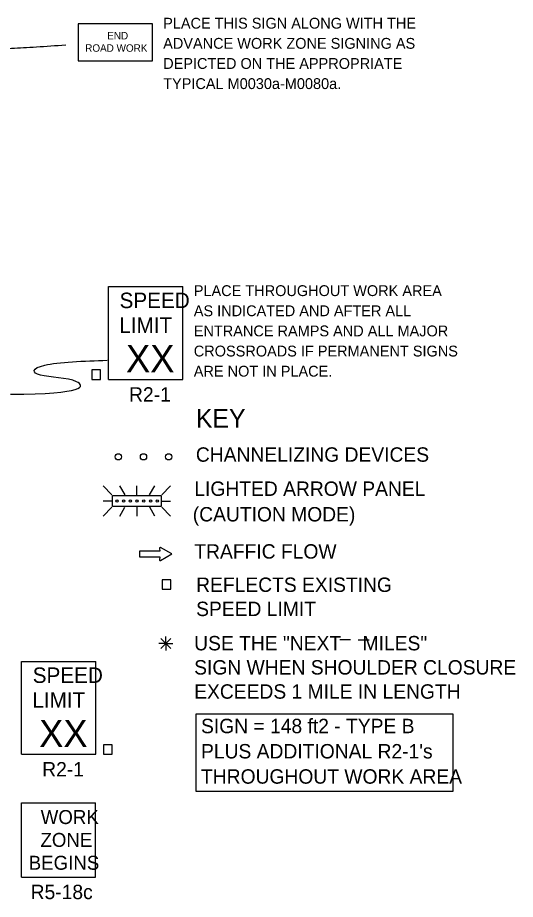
# Model space of a CAD drawing. Extents: x 16738 to 18471, y 7027 to 8193.
# Drawn here: x 17125 to 17446, y 7606 to 8175 of the extents above; entities that cross this region are included whole.
import ezdxf

# ---------------------------------------------------------------- set-up
doc = ezdxf.new("R2010")
doc.units = 0
for name, color, linetype in [('MT_SCRATCH_LEVEL_E', 7, 'Continuous'), ('TRAFFIC_SIGNS_PR', 7, 'Continuous'), ('TYPICAL_TEXT_DIMEN_EX', 7, 'Continuous'), ('TYPICAL_TEXT_DIMEN_PR', 7, 'Continuous')]:
    doc.layers.add(name, color=color, linetype=linetype)

msp = doc.modelspace()

# ---------------------------------------------------------------- linework, layer by layer
at = {"layer": 'MT_SCRATCH_LEVEL_E'}
for p, q in [((17216.66, 7830.53), (17203.4, 7830.53)), ((17203.4, 7830.53), (17203.4, 7826.79)), ((17216.66, 7830.53), (17203.4, 7830.53)), ((17203.4, 7830.53), (17203.4, 7826.79)), ((17216.34, 7832.3), (17216.66, 7830.53)), ((17216.34, 7832.3), (17216.66, 7830.53)), ((17224.27, 7828.68), (17217.03, 7832.79)), ((17224.27, 7828.68), (17217.03, 7832.79)), ((17217.03, 7824.53), (17224.27, 7828.68)), ((17217.03, 7824.53), (17224.27, 7828.68)), ((17203.4, 7826.79), (17216.66, 7826.79)), ((17203.4, 7826.79), (17216.66, 7826.79)), ((17216.66, 7826.79), (17216.34, 7825.01)), ((17216.66, 7826.79), (17216.34, 7825.01))]:
    msp.add_line(p, q, dxfattribs=at)
for centre, start, end in [((17216.8, 7832.38), 60.4248, 189.9638), ((17216.8, 7832.38), 60.4248, 189.9638), ((17216.8, 7824.94), 170.0362, 299.7731), ((17216.8, 7824.94), 170.0362, 299.7731)]:
    msp.add_arc(centre, 0.463, start, end, dxfattribs=at)
at = {"layer": 'TRAFFIC_SIGNS_PR'}
for p, q in [((17183.35, 8001.34), (17231.35, 8001.34)), ((17183.35, 7941.34), (17183.35, 8001.34)), ((17231.35, 7941.34), (17231.35, 8001.34)), ((17183.35, 7941.34), (17231.35, 7941.34)), ((17179.91, 7872.58), (17185.55, 7866.95)), ((17194.09, 7866.95), (17190.83, 7872.59)), ((17201.72, 7866.95), (17201.72, 7872.59)), ((17209.99, 7866.95), (17213.24, 7872.59)), ((17217.89, 7866.95), (17223.53, 7872.59)), ((17185.55, 7862.88), (17179.91, 7862.88)), ((17188.82, 7862.88), (17188.82, 7862.88)), ((17193.17, 7862.88), (17193.17, 7862.88)), ((17197.52, 7862.88), (17197.52, 7862.88)), ((17201.87, 7862.88), (17201.87, 7862.88)), ((17206.21, 7862.88), (17206.21, 7862.88)), ((17210.56, 7862.88), (17210.56, 7862.88)), ((17214.91, 7862.88), (17214.91, 7862.88)), ((17217.89, 7862.88), (17223.53, 7862.88)), ((17179.91, 7853.18), (17185.55, 7858.82)), ((17190.78, 7853.18), (17194.03, 7858.82)), ((17201.72, 7858.82), (17201.72, 7853.18)), ((17213.29, 7853.18), (17210.04, 7858.82)), ((17217.89, 7858.82), (17223.53, 7853.18)), ((17127.24, 7759.34), (17175.24, 7759.34)), ((17127.24, 7699.34), (17127.24, 7759.34)), ((17175.24, 7699.34), (17175.24, 7759.34)), ((17127.24, 7699.34), (17175.24, 7699.34)), ((17127.12, 7620.11), (17127.12, 7668.11)), ((17127.12, 7668.11), (17175.12, 7668.11)), ((17175.12, 7620.11), (17175.12, 7668.11)), ((17127.12, 7620.11), (17175.12, 7620.11))]:
    msp.add_line(p, q, dxfattribs=at)
for points in [[(17163.85, 8147.03), (17211.85, 8147.03), (17211.85, 8171.03), (17163.85, 8171.03)], [(17172.74, 7941.34), (17178.33, 7941.34), (17178.33, 7947.51), (17172.74, 7947.51)], [(17217.43, 7859.28), (17186.01, 7859.28), (17186.01, 7866.48), (17217.43, 7866.48)], [(17218.08, 7805.86), (17223.67, 7805.86), (17223.67, 7812.03), (17218.08, 7812.03)], [(17180.26, 7699.34), (17185.85, 7699.34), (17185.85, 7705.51), (17180.26, 7705.51)]]:
    msp.add_lwpolyline(points, close=True, dxfattribs=at)
for centre, radius in [((17189.71, 7891.4), 2), ((17206.01, 7891.4), 2), ((17222.31, 7891.4), 2), ((17188.86, 7862.88), 0.758), ((17193.17, 7862.88), 0.758), ((17197.52, 7862.88), 0.758), ((17201.87, 7862.88), 0.758), ((17206.21, 7862.88), 0.758), ((17210.56, 7862.88), 0.758), ((17214.91, 7862.88), 0.758)]:
    msp.add_circle(centre, radius, dxfattribs=at)
msp.add_open_spline([(17155.78, 8157.21), (17040.56, 8148.97), (17154.47, 8176.55), (17056.53, 8174.38)], degree=2, dxfattribs=at)
at = {"layer": 'TYPICAL_TEXT_DIMEN_EX'}
for p, q in [((17332.79, 7773.4), (17339.79, 7773.4)), ((17344.74, 7773.24), (17351.74, 7773.24))]:
    msp.add_line(p, q, dxfattribs=at)
msp.add_lwpolyline([(17240.03, 7725.38), (17405.73, 7725.38), (17405.73, 7675.31), (17240.03, 7675.31)], close=True, dxfattribs=at)
at = {"layer": 'TYPICAL_TEXT_DIMEN_PR'}
for p, q in [((17217.22, 7774.07), (17223.6, 7767.69)), ((17223.6, 7774.07), (17217.22, 7767.69)), ((17220.41, 7770.88), (17220.41, 7775.33)), ((17220.41, 7770.88), (17215.88, 7770.88)), ((17220.41, 7770.88), (17223.6, 7770.88)), ((17220.41, 7770.88), (17224.89, 7770.88)), ((17220.41, 7770.88), (17220.41, 7766.38))]:
    msp.add_line(p, q, dxfattribs=at)
msp.add_open_spline([(17120.14, 7931.87), (17168.61, 7931.87), (17168.61, 7942.62), (17133.69, 7942.62), (17133.69, 7951.67), (17167.9, 7953.43), (17182.62, 7953.72)], degree=3, dxfattribs=at)

# ---------------------------------------------------------------- texts
at = {"layer": 'TRAFFIC_SIGNS_PR'}
for s, height, p in [('PLACE THIS SIGN ALONG WITH THE', 7, (17218.73, 8167.88)), ('END', 4.789, (17182.6, 8160.94)), ('ADVANCE WORK ZONE SIGNING AS', 7, (17218.73, 8154.88)), ('ROAD WORK', 4.789, (17168.36, 8152.96)), ('DEPICTED ON THE APPROPRIATE', 7, (17218.73, 8141.88)), ('TYPICAL M0030a-M0080a.', 7, (17218.73, 8128.88)), ('PLACE THROUGHOUT WORK AREA', 7, (17238.5, 7995.2)), ('SPEED', 10, (17190.55, 7987.42)), ('AS INDICATED AND AFTER ALL', 7, (17238.5, 7982.2)), ('LIMIT', 10, (17190.35, 7971.42)), ('ENTRANCE RAMPS AND ALL MAJOR', 7, (17238.5, 7969.2)), ('XX', 17.538, (17194.74, 7946.04)), ('CROSSROADS IF PERMANENT SIGNS', 7, (17238.5, 7956.2)), ('ARE NOT IN PLACE.', 7, (17238.5, 7943.2)), ('R2-1', 9.3, (17196.69, 7927.04)), ('SPEED', 10, (17134.45, 7745.42)), ('LIMIT', 10, (17134.25, 7729.42)), ('XX', 17.538, (17138.63, 7704.04)), ('R2-1', 9.3, (17140.59, 7685.04)), ('WORK', 9.021, (17139.62, 7654.32)), ('ZONE', 9.021, (17139.47, 7639.56)), ('BEGINS', 9.021, (17131.88, 7624.79)), ('R5-18c', 9.3, (17133.13, 7605.81))]:
    msp.add_text(s, height=height, dxfattribs=at).set_placement(p)
at = {"layer": 'TYPICAL_TEXT_DIMEN_EX'}
for s, height, p in [('KEY', 12, (17239.84, 7910.29)), ('CHANNELIZING DEVICES', 9.3, (17239.84, 7888.24)), ('LIGHTED ARROW PANEL', 9.3, (17238.84, 7866.19)), ('(CAUTION MODE)', 9.3, (17237.85, 7849.69)), ('TRAFFIC FLOW', 9.3, (17238.84, 7825.69)), ('REFLECTS EXISTING', 9.3, (17240.01, 7804.18)), ('SPEED LIMIT', 9.3, (17240.01, 7788.58)), ('USE THE "NEXT    MILES"', 9.3, (17238.75, 7766.44)), ('SIGN WHEN SHOULDER CLOSURE', 9.3, (17238.75, 7750.84)), ('EXCEEDS 1 MILE IN LENGTH', 9.3, (17238.75, 7735.24)), ('SIGN = 148 ft2 - TYPE B', 9.3, (17243.17, 7712.97)), ("PLUS ADDITIONAL R2-1's", 9.3, (17243.17, 7696.67)), ('THROUGHOUT WORK AREA', 9.3, (17243.17, 7680.37))]:
    msp.add_text(s, height=height, dxfattribs=at).set_placement(p)

doc.saveas('drawing.dxf')
